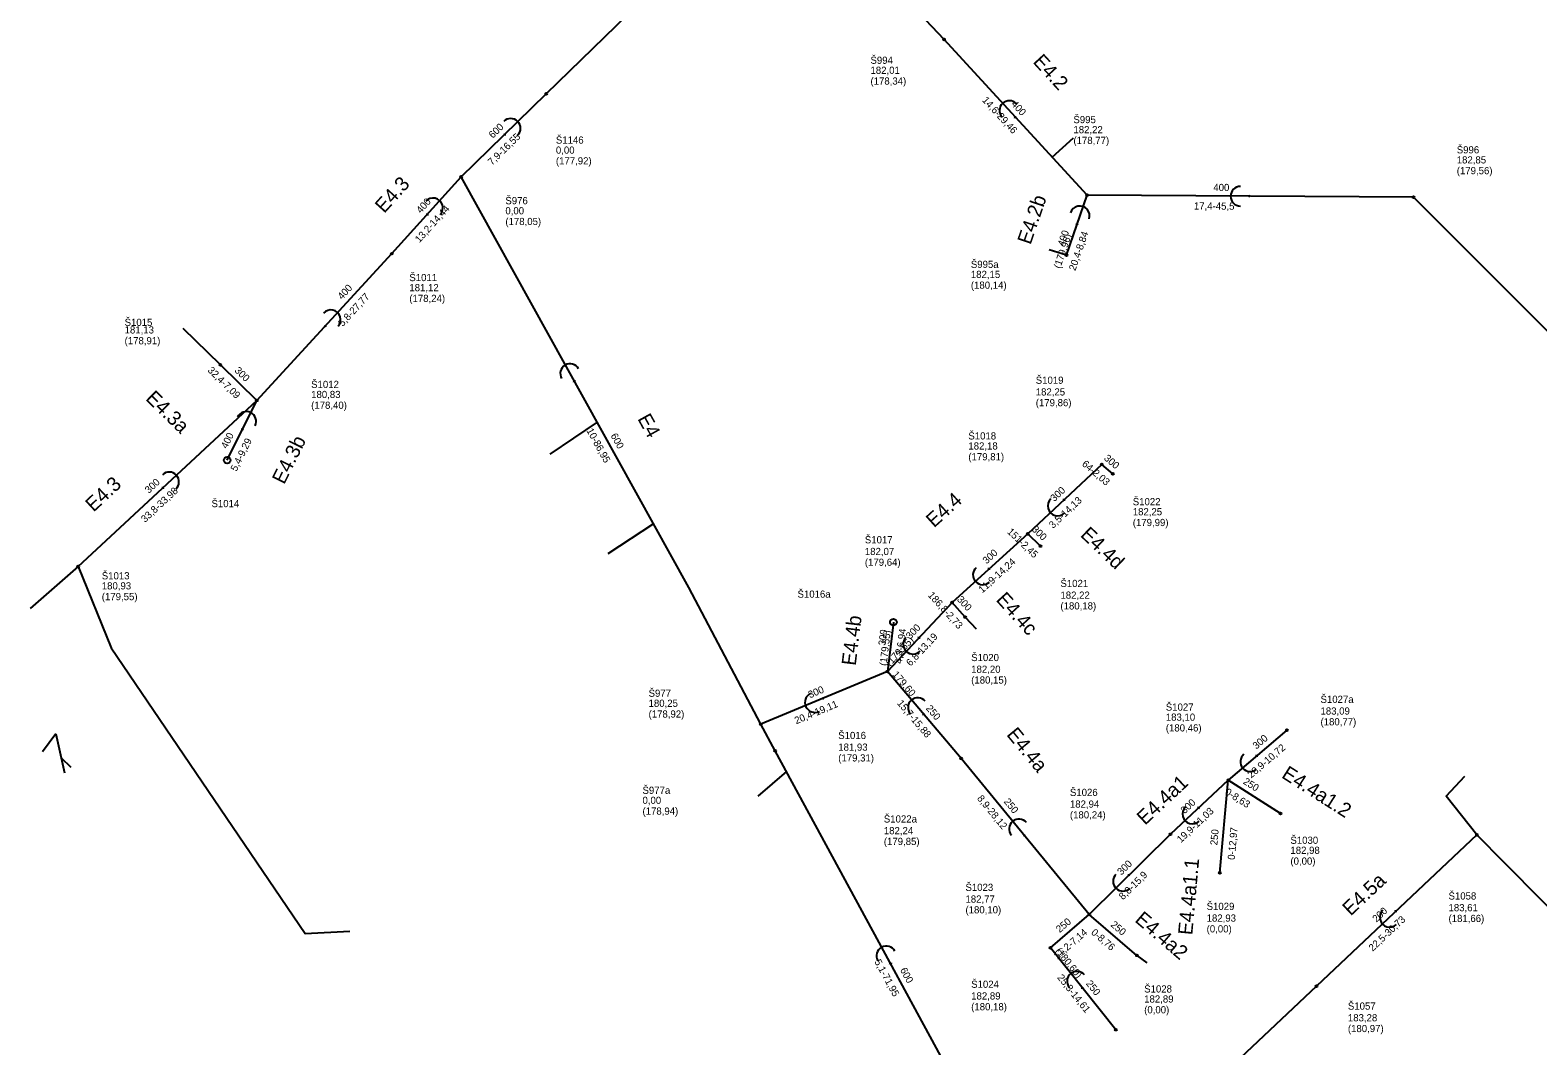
# Model space of a CAD drawing. Extents: x -548529 to -543591, y -1201432 to -1192608.
# Drawn here: x -544543.9 to -544333.8, y -1193949.5 to -1193808 of the extents above; entities that cross this region are included whole.
import ezdxf

# ---------------------------------------------------------------- set-up
doc = ezdxf.new("R2010")
doc.units = 0
for name, color, linetype in [('C3D_Bod-Značky', 7, 'Continuous'), ('C3D_Koridor', 7, 'Continuous'), ('C3D_Křižovatka', 7, 'Continuous'), ('C3D_Netisknutelná', 7, 'Continuous'), ('C3D_PP-zobrazeni v PR', 7, 'Continuous'), ('C3D_PR-Popisek', 7, 'Continuous'), ('C3D_SPR-Popisek', 7, 'Continuous'), ('C3D_Tlakove_potrubi_Popis', 7, 'Continuous'), ('C3D_ZPR-Formaty', 7, 'Continuous')]:
    doc.layers.add(name, color=color, linetype=linetype)

# ---------------------------------------------------------------- blocks, each defined once
blk = doc.blocks.new('100')
at = {"layer": 'Defpoints'}
blk.add_circle((0, 0), 0.127, dxfattribs=at)
blk = doc.blocks.new('101')
at = {"layer": 'Defpoints'}
blk.add_circle((0, 0), 0.463, dxfattribs=at)
blk = doc.blocks.new('86')
at = {"layer": 'Defpoints'}
blk.add_lwpolyline([(0.08, 0.14), (0.19, 0), (0.08, -0.14)], dxfattribs=at)
blk.add_arc((1.37, 0), 1.37, 270, 90, dxfattribs=at)
blk = doc.blocks.new('91')
at = {"layer": 'Defpoints'}
blk.add_lwpolyline([(0.08, 0.14), (0.19, 0), (0.08, -0.14)], dxfattribs=at)
blk.add_arc((1.37, 0), 1.37, 270, 90, dxfattribs=at)

msp = doc.modelspace()

# ---------------------------------------------------------------- linework, layer by layer
at = {"layer": 'C3D_Bod-Značky'}
for points in [[(-544471.955, -1193816.856), (-544439.378, -1193785.138)], [(-544416.53, -1193809.28), (-544439.378, -1193785.138)], [(-544396.6, -1193830.97), (-544416.53, -1193809.28)], [(-544483.813, -1193828.401), (-544471.955, -1193816.856)], [(-544493.495, -1193839.115), (-544483.813, -1193828.401)], [(-544442.071, -1193904.67), (-544452.092, -1193885.632), (-544483.813, -1193828.401)], [(-544399.47, -1193839.33), (-544396.6, -1193830.97)], [(-544351.104, -1193831.259), (-544396.6, -1193830.97)], [(-544298.88, -1193883.424), (-544351.104, -1193831.259)], [(-544512.297, -1193859.556), (-544493.495, -1193839.115)], [(-544517.372, -1193854.603), (-544512.297, -1193859.556)], [(-544537.181, -1193882.694), (-544532.629, -1193878.462), (-544512.297, -1193859.556)], [(-544516.425, -1193867.877), (-544512.297, -1193859.556)], [(-544394.56, -1193868.47), (-544404.85, -1193878.15)], [(-544393.02, -1193869.79), (-544394.56, -1193868.47)], [(-544404.85, -1193878.15), (-544415.412, -1193887.705)], [(-544403.08, -1193879.84), (-544404.85, -1193878.15)], [(-544415.412, -1193887.705), (-544424.431, -1193897.332)], [(-544413.576, -1193889.729), (-544415.412, -1193887.705)], [(-544423.594, -1193890.446), (-544424.431, -1193897.332)], [(-544424.431, -1193897.332), (-544442.071, -1193904.67)], [(-544414.139, -1193909.424), (-544424.431, -1193897.332)], [(-544440.067, -1193908.361), (-544442.071, -1193904.67)], [(-544368.75, -1193905.5), (-544376.916, -1193912.452)], [(-544405.73, -1193971.59), (-544440.067, -1193908.361)], [(-544396.294, -1193931.152), (-544414.139, -1193909.424)], [(-544376.916, -1193912.452), (-544384.969, -1193919.994)], [(-544378.098, -1193925.372), (-544376.916, -1193912.452)], [(-544369.644, -1193917.092), (-544376.916, -1193912.452)], [(-544384.969, -1193919.994), (-544396.294, -1193931.152)], [(-544342.273, -1193920.062), (-544364.634, -1193941.139)], [(-544401.707, -1193935.809), (-544396.294, -1193931.152)], [(-544389.65, -1193936.863), (-544396.294, -1193931.152)], [(-544392.582, -1193947.218), (-544401.707, -1193935.809)], [(-544364.634, -1193941.139), (-544390.782, -1193965.807)]]:
    msp.add_lwpolyline(points, dxfattribs=at)
at = {"layer": 'C3D_Koridor'}
for points in [[(-544401.459, -1193825.681), (-544398.494, -1193822.977)], [(-544399.47, -1193839.33), (-544401.895, -1193838.582)], [(-544517.372, -1193854.603), (-544522.534, -1193849.561)], [(-544464.854, -1193862.606), (-544471.458, -1193867.059)], [(-544457.021, -1193876.74), (-544463.365, -1193880.915)], [(-544537.181, -1193882.694), (-544543.874, -1193888.555)], [(-544537.181, -1193882.694), (-544532.602, -1193894.011), (-544505.57, -1193933.794), (-544499.311, -1193933.488)], [(-544413.576, -1193889.729), (-544412.076, -1193891.353)], [(-544540.306, -1193905.988), (-544542.171, -1193908.523)], [(-544540.306, -1193905.988), (-544539.08, -1193911.415)], [(-544539.544, -1193909.362), (-544538.214, -1193910.621)], [(-544438.501, -1193911.243), (-544442.48, -1193914.668)], [(-544342.273, -1193920.062), (-544346.575, -1193914.686), (-544343.972, -1193911.888)], [(-544342.273, -1193920.062), (-544338.504, -1193923.885), (-544327.773, -1193934.764), (-544324.71, -1193931.499)], [(-544389.65, -1193936.863), (-544388.284, -1193937.907)]]:
    msp.add_lwpolyline(points, dxfattribs=at)

# ---------------------------------------------------------------- block references
at = {"layer": 'C3D_PP-zobrazeni v PR'}
for name, p, xscale, yscale, rotation in [('100', (-544416.53, -1193809.28), 1.0000000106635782, 1.0000000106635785, 134.00000165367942), ('100', (-544471.955, -1193816.856), 0.999999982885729, 0.9999999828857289, -135), ('100', (-544483.813, -1193828.401), 1.00000000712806, 1.00000000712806, -133.00000056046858), ('100', (-544396.6, -1193830.97), 1.0225848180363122, 1.0225848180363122, 154.18102564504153), ('100', (-544351.104, -1193831.259), 1.025136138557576, 1.025136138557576, 154.7492415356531), ('100', (-544493.495, -1193839.115), 1.0000000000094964, 1.0000000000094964, -132.0000013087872), ('100', (-544399.47, -1193839.33), 1.000000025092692, 1.0000000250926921, 71.99999997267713), ('100', (-544517.372, -1193854.603), 1.0000000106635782, 1.0000000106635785, -44.00000165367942), ('100', (-544512.297, -1193859.556), 0.9999999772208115, 0.9999999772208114, -79.99999971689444), ('101', (-544516.425, -1193867.877), 1.0000000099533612, 1.0000000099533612, -116.000000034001), ('100', (-544394.56, -1193868.47), 1.00000001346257, 1.0000000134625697, -178.0000000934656), ('100', (-544393.02, -1193869.79), 1.0000000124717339, 1.0000000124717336, -40.00000131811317), ('100', (-544404.85, -1193878.15), 1.00000000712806, 1.00000000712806, -136.99999943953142), ('100', (-544403.08, -1193879.84), 1.00000000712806, 1.00000000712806, -43.0000005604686), ('100', (-544537.181, -1193882.694), 1.0000000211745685, 1.0000000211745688, 81.00000039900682), ('100', (-544415.412, -1193887.705), 0.999999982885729, 0.9999999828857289, -135), ('101', (-544423.594, -1193890.446), 1.0011217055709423, 1.0011217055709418, 83.41739016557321), ('100', (-544413.576, -1193889.729), 1.00000000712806, 1.00000000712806, -46.99999943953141), ('100', (-544424.431, -1193897.332), 1.000000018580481, 1.000000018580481, -144.99999976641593), ('100', (-544442.071, -1193904.67), 1.0000000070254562, 1.0000000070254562, 118.99999892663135), ('100', (-544368.75, -1193905.5), 1.0000000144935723, 1.0000000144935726, 40.99999910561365), ('100', (-544440.067, -1193908.361), 1.0000000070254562, 1.0000000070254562, 118.99999892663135), ('100', (-544414.139, -1193909.424), 1.0000000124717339, 1.0000000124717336, 130.0000013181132), ('100', (-544376.916, -1193912.452), 1.0011217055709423, 1.0011217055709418, -173.41739016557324), ('100', (-544369.644, -1193917.092), 0.9999999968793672, 0.9999999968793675, -32.00000027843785), ('100', (-544384.969, -1193919.994), 1.0000000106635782, 1.0000000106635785, -135.99999834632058), ('100', (-544342.273, -1193920.062), 1.0000000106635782, 1.0000000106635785, -135.99999834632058), ('100', (-544378.098, -1193925.372), 1.000000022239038, 1.0000000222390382, 85.00000001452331), ('100', (-544396.294, -1193931.152), 1.0002788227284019, 1.0002788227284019, 176.70930040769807), ('100', (-544401.707, -1193935.809), 1.000000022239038, 1.0000000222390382, 85.00000001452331), ('100', (-544389.65, -1193936.863), 1.0000000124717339, 1.0000000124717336, -40.00000131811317), ('100', (-544364.634, -1193941.139), 1.0000000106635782, 1.0000000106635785, -135.99999834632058), ('100', (-544392.582, -1193947.218), 1.000000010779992, 1.0000000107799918, -51.00000108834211)]:
    msp.add_blockref(name, p, dxfattribs=dict(at, xscale=xscale, yscale=yscale, rotation=rotation))
at = {"layer": 'C3D_SPR-Popisek'}
for name, p, xscale, yscale, rotation in [('91', (-544406.509, -1193820.186), 1.00000000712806, 1.00000000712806, 133.00000056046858), ('91', (-544477.884, -1193822.629), 0.999999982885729, 0.9999999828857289, 45), ('86', (-544488.654, -1193833.758), 1.0000000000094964, 1.0000000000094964, 47.99999869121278), ('91', (-544398.035, -1193835.15), 1.000000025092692, 1.0000000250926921, 71.99999997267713), ('86', (-544502.896, -1193849.336), 1.0000000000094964, 1.0000000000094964, 47.99999869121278), ('91', (-544467.952, -1193857.016), 0.9999999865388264, 0.9999999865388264, 120.00000044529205), ('86', (-544514.361, -1193863.716), 1.0000000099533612, 1.0000000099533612, 63.999999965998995), ('86', (-544525.505, -1193871.838), 1.00000000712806, 1.00000000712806, 43.0000005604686), ('91', (-544399.705, -1193873.31), 1.0000000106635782, 1.0000000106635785, -135.99999834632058), ('91', (-544410.131, -1193882.928), 1.00000000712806, 1.00000000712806, -136.99999943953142), ('91', (-544419.921, -1193892.518), 1.00000000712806, 1.00000000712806, -133.00000056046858), ('91', (-544433.251, -1193901.001), 1.0225848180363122, 1.0225848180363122, -154.18102564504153), ('91', (-544419.285, -1193903.378), 1.0000000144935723, 1.0000000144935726, 130.99999910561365), ('91', (-544372.833, -1193908.976), 1.0000000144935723, 1.0000000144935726, -139.00000089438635), ('91', (-544380.942, -1193916.223), 1.0000000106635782, 1.0000000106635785, -135.99999834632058), ('91', (-544405.216, -1193920.288), 1.0000000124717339, 1.0000000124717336, 130.0000013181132), ('91', (-544390.632, -1193925.573), 0.999999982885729, 0.9999999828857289, -135), ('91', (-544353.454, -1193930.6), 1.0000000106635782, 1.0000000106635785, -135.99999834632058), ('91', (-544423.9, -1193938.13), 1.0000000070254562, 1.0000000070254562, 118.99999892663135), ('91', (-544397.144, -1193941.514), 1.000000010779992, 1.0000000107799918, 128.99999891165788)]:
    msp.add_blockref(name, p, dxfattribs=dict(at, xscale=xscale, yscale=yscale, rotation=rotation))
at = {"layer": 'C3D_SPR-Popisek', "rotation": 180}
msp.add_blockref('91', (-544373.852, -1193831.115), dxfattribs=at)

# ---------------------------------------------------------------- texts
at = {"layer": 'C3D_Křižovatka'}
for s, p in [('Š994', (-544426.78, -1193812.67)), ('Š995', (-544398.5, -1193820.94)), ('Š1146', (-544470.615, -1193823.786)), ('Š996', (-544345.084, -1193825.149)), ('Š976', (-544477.653, -1193832.231)), ('Š995a', (-544412.79, -1193841.1)), ('Š1011', (-544491.035, -1193842.945)), ('Š1015', (-544530.712, -1193849.183)), ('Š1012', (-544504.717, -1193857.826)), ('Š1019', (-544403.75, -1193857.24)), ('Š1018', (-544413.14, -1193865)), ('Š1014', (-544518.605, -1193874.427)), ('Š1022', (-544390.23, -1193874.16)), ('Š1017', (-544427.562, -1193879.465)), ('Š1013', (-544533.891, -1193884.484)), ('Š1016a', (-544436.944, -1193887.036)), ('Š1021', (-544400.31, -1193885.55)), ('Š1020', (-544412.746, -1193895.869)), ('Š977', (-544457.701, -1193900.84)), ('Š1027a', (-544364.07, -1193901.69)), ('Š1027', (-544385.626, -1193902.772)), ('Š1016', (-544431.271, -1193906.722)), ('Š977a', (-544458.547, -1193914.361)), ('Š1026', (-544398.989, -1193914.654)), ('Š1022a', (-544424.919, -1193918.354)), ('Š1030', (-544368.264, -1193921.322)), ('Š1023', (-544413.544, -1193927.882)), ('Š1058', (-544346.233, -1193929.082)), ('Š1029', (-544379.938, -1193930.532)), ('Š1024', (-544412.747, -1193941.379)), ('Š1028', (-544388.64, -1193942.033)), ('Š1057', (-544360.254, -1193944.419))]:
    msp.add_text(s, height=1, dxfattribs=at).set_placement(p)
at = {"layer": 'C3D_Netisknutelná'}
for s, rotation, p in [('E4.2', 312.58, (-544404.246, -1193812.458)), ('E4.3', 47.9, (-544494.538, -1193833.588)), ('E4.2b', 71.05, (-544404.482, -1193837.964)), ('E4.3a', 315.7, (-544527.901, -1193859.41)), ('E4', 299, (-544459.294, -1193862.104)), ('E4.3b', 63.61, (-544508.48, -1193871.359)), ('E4.3', 42.92, (-544535.039, -1193875.185)), ('E4.4', 42.13, (-544417.927, -1193877.372)), ('E4.4d', 316.32, (-544397.644, -1193878.408)), ('E4.4c', 312.21, (-544409.392, -1193887.385)), ('E4.4b', 83.07, (-544428.839, -1193896.57)), ('E4.4a', 309.4, (-544407.912, -1193906.134)), ('E4.4a1.2', 327.46, (-544369.627, -1193912.025)), ('E4.4a1', 43.12, (-544388.525, -1193918.809)), ('E4.4a1.1', 84.77, (-544381.943, -1193934.083)), ('E4.5a', 43.31, (-544359.872, -1193931.453)), ('E4.4a2', 319.32, (-544390.062, -1193932.076))]:
    msp.add_text(s, height=2, rotation=rotation, dxfattribs=at).set_placement(p)
at = {"layer": 'C3D_PR-Popisek'}
for s, rotation, p in [('400', 312.58, (-544407.241, -1193818.352)), ('600', 44.23, (-544479.401, -1193823.125)), ('400', 359.64, (-544379.008, -1193830.382)), ('400', 47.9, (-544489.441, -1193833.582)), ('400', 71.05, (-544399.808, -1193838.167)), ('400', 47.39, (-544500.412, -1193845.597)), ('300', 315.7, (-544515.47, -1193855.479)), ('400', 63.61, (-544516.454, -1193866.358)), ('600', 299, (-544463.026, -1193864.46)), ('300', 319.4, (-544394.328, -1193867.743)), ('300', 42.92, (-544527.335, -1193872.579)), ('300', 43.25, (-544401.16, -1193873.724)), ('300', 316.32, (-544404.389, -1193877.619)), ('300', 42.13, (-544410.614, -1193882.417)), ('300', 312.21, (-544414.801, -1193887.334)), ('300', 83.07, (-544424.703, -1193893.743)), ('300', 46.87, (-544421.236, -1193892.905)), ('300', 22.59, (-544435.216, -1193901.063)), ('250', 310.4, (-544419.118, -1193902.499)), ('300', 40.41, (-544373.011, -1193908.212)), ('250', 327.46, (-544374.942, -1193912.881)), ('250', 309.4, (-544408.26, -1193915.472)), ('300', 43.12, (-544383.006, -1193917.204)), ('250', 84.77, (-544378.454, -1193921.559)), ('300', 44.57, (-544391.818, -1193925.757)), ('200', 43.31, (-544356.282, -1193932.31)), ('250', 40.71, (-544400.409, -1193933.765)), ('250', 319.32, (-544393.395, -1193932.716)), ('600', 298.5, (-544422.694, -1193938.882)), ('250', 308.65, (-544396.813, -1193940.81))]:
    msp.add_text(s, height=1, rotation=rotation, dxfattribs=at).set_placement(p)
at = {"layer": 'C3D_Tlakove_potrubi_Popis'}
for s, p in [('(178,34)', (-544426.78, -1193815.57)), ('182,01 ', (-544426.78, -1193814.07)), ('(178,77)', (-544398.5, -1193823.84)), ('182,22 ', (-544398.5, -1193822.34)), ('0,00 ', (-544470.615, -1193825.186)), ('(177,92)', (-544470.615, -1193826.686)), ('(179,56)', (-544345.084, -1193828.049)), ('182,85 ', (-544345.084, -1193826.549)), ('0,00 ', (-544477.653, -1193833.631)), ('(178,05)', (-544477.653, -1193835.131)), ('182,15 ', (-544412.79, -1193842.5)), ('181,12 ', (-544491.035, -1193844.345)), ('(180,14)', (-544412.79, -1193844)), ('(178,24)', (-544491.035, -1193845.845)), ('181,13 ', (-544530.712, -1193850.233)), ('(178,91)', (-544530.712, -1193851.733)), ('180,83 ', (-544504.717, -1193859.226)), ('182,25 ', (-544403.75, -1193858.87)), ('(178,40)', (-544504.717, -1193860.726)), ('(179,86)', (-544403.75, -1193860.37)), ('(179,81)', (-544413.14, -1193867.9)), ('182,18 ', (-544413.14, -1193866.4)), ('182,25 ', (-544390.23, -1193875.56)), ('(179,99)', (-544390.23, -1193877.06)), ('(179,64)', (-544427.562, -1193882.595)), ('182,07 ', (-544427.562, -1193881.095)), ('180,93 ', (-544533.891, -1193885.884)), ('182,22 ', (-544400.31, -1193887.18)), ('(179,55)', (-544533.891, -1193887.384)), ('(180,18)', (-544400.31, -1193888.68)), ('182,20 ', (-544412.746, -1193897.499)), ('(180,15)', (-544412.746, -1193898.999)), ('(178,92)', (-544457.701, -1193903.74)), ('180,25 ', (-544457.701, -1193902.24)), ('183,09 ', (-544364.07, -1193903.32)), ('(180,46)', (-544385.626, -1193905.672)), ('183,10 ', (-544385.626, -1193904.172)), ('(180,77)', (-544364.07, -1193904.82)), ('(179,31)', (-544431.271, -1193909.852)), ('181,93 ', (-544431.271, -1193908.352)), ('0,00 ', (-544458.547, -1193915.761)), ('182,94 ', (-544398.989, -1193916.284)), ('(178,94)', (-544458.547, -1193917.261)), ('(180,24)', (-544398.989, -1193917.784)), ('182,24 ', (-544424.919, -1193919.984)), ('(179,85)', (-544424.919, -1193921.484)), ('182,98 ', (-544368.264, -1193922.722)), ('(0,00)', (-544368.264, -1193924.222)), ('(180,10)', (-544413.544, -1193931.012)), ('182,77 ', (-544413.544, -1193929.512)), ('183,61 ', (-544346.233, -1193930.712)), ('182,93 ', (-544379.938, -1193932.162)), ('(181,66)', (-544346.233, -1193932.212)), ('(0,00)', (-544379.938, -1193933.662)), ('182,89 ', (-544412.747, -1193943.009)), ('182,89 ', (-544388.64, -1193943.433)), ('(180,18)', (-544412.747, -1193944.509)), ('(0,00)', (-544388.64, -1193944.933)), ('183,28 ', (-544360.254, -1193946.049)), ('(180,97)', (-544360.254, -1193947.549))]:
    msp.add_text(s, height=1, dxfattribs=at).set_placement(p)
at = {"layer": 'C3D_ZPR-Formaty'}
for s, rotation, p in [('14,6-29,46', 312.58, (-544411.283, -1193817.799)), ('7,9-16,55', 44.23, (-544479.519, -1193826.872)), ('13,2-14,44', 47.9, (-544489.625, -1193837.667)), ('17,4-45,5', 359.64, (-544381.716, -1193832.965)), ('  (179,96)   ', 71.05, (-544400.589, -1193841.971)), ('20,4-8,84', 71.05, (-544398.23, -1193841.565)), ('5,8-27,77', 47.39, (-544500.32, -1193849.342)), ('32,4-7,09', 315.7, (-544519.22, -1193855.455)), ('5,4-9,29', 63.61, (-544515.12, -1193869.526)), ('10-86,95', 299, (-544466.391, -1193863.751)), ('64-2,03', 319.4, (-544397.396, -1193868.544)), ('33,8-33,98', 42.92, (-544527.868, -1193876.629)), ('3,5-14,13', 43.25, (-544401.348, -1193877.464)), ('151-2,45', 316.32, (-544407.813, -1193877.948)), ('11,9-14,24', 42.13, (-544411.201, -1193886.459)), ('186,8-2,73', 312.21, (-544418.844, -1193886.751)), ('  (179,55)   ', 83.07, (-544424.63, -1193897.308)), ('  (179,55)   ', 46.87, (-544424.577, -1193897.195)), ('4,3-6,94', 83.07, (-544422.395, -1193896.285)), ('6,8-13,19', 46.87, (-544421.19, -1193896.652)), ('  179,60   ', 310.4, (-544424.279, -1193897.202)), ('20,4-19,11', 22.59, (-544437.127, -1193904.676)), ('15,7-15,88', 310.4, (-544423.135, -1193901.778)), ('28,9-10,72', 40.41, (-544373.732, -1193912.23)), ('8,9-28,12', 309.4, (-544411.986, -1193915.034)), ('0-8,63', 327.46, (-544377.484, -1193914.345)), ('19,9-11,03', 43.12, (-544383.528, -1193921.249)), ('0-12,97', 84.77, (-544376.024, -1193923.589)), ('8,8-15,9', 44.57, (-544391.598, -1193929.193)), ('22,5-30,73', 43.31, (-544356.793, -1193936.36)), ('11,2-7,14', 40.71, (-544400.752, -1193937.497)), ('0-8,76', 319.32, (-544396.122, -1193933.808)), ('  (180,60)   ', 308.65, (-544401.551, -1193935.684)), ('5,1-71,95', 298.5, (-544426.273, -1193937.747)), ('25,3-14,61', 308.65, (-544400.814, -1193939.974))]:
    msp.add_text(s, height=1, rotation=rotation, dxfattribs=at).set_placement(p)

doc.saveas('drawing.dxf')
